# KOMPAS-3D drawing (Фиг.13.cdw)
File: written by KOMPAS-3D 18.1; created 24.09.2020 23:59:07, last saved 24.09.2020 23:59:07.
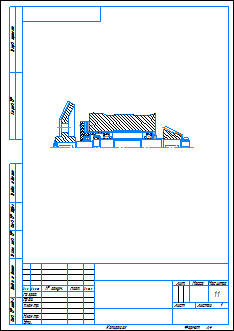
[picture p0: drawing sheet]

Sheet 1: A4, portrait

Document properties: Автор: user; Полное имя файла: C:\Users\user\Desktop\Задания\Фиг.13.cdw

Title block, sheet 1: scale: 1:1; Количество листов документа: 1; Форматы листов документа: A4

Dimensions and other numbers on the sheet: 1:1; 1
